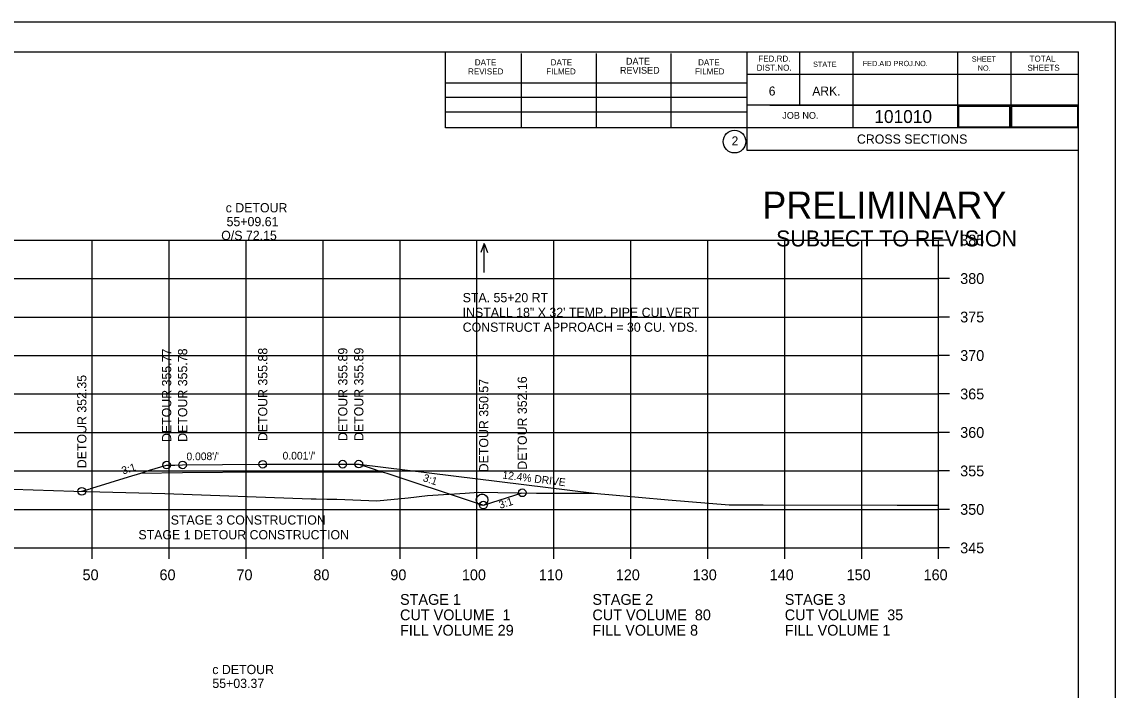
# Model space of a CAD drawing. Extents: x 1630712 to 1632516, y 782146 to 785403.
# Drawn here: x 1632373.8 to 1632515.9, y 784036.5 to 784123.3 of the extents above; entities that cross this region are included whole.
import ezdxf

# ---------------------------------------------------------------- set-up
doc = ezdxf.new("R2010")
doc.units = 0
for name, color, linetype in [('Notes', 7, 'Continuous'), ('Page Number', 7, 'Continuous'), ('R_Axis', 7, 'Continuous'), ('R_Axis Annot', 7, 'Continuous'), ('R_Border', 7, 'Continuous'), ('R_Border Notes', 7, 'Continuous'), ('R_Border Prem', 7, 'Continuous'), ('R_Culvert', 7, 'Continuous'), ('R_Culvert Temporary', 7, 'Continuous'), ('R_Culvert Temporary Annot', 7, 'Continuous'), ('R_Detour Subgrade', 7, 'Continuous'), ('R_Detour Surface', 7, 'Continuous'), ('R_Exist Surface', 7, 'Continuous'), ('R_Grid', 7, 'Continuous'), ('R_No Plot', 7, 'Continuous'), ('R_Water Annot', 7, 'Continuous'), ('R_Xsect Elev Detour', 7, 'Continuous'), ('R_Xsect Slope', 7, 'Continuous'), ('Total_Pages', 7, 'Continuous')]:
    doc.layers.add(name, color=color, linetype=linetype)

msp = doc.modelspace()

# ---------------------------------------------------------------- linework, layer by layer
at = {"layer": 'Page Number'}
msp.add_lwpolyline([(1632495.54, 784109.69), (1632502.21, 784109.69), (1632502.21, 784112.33), (1632495.54, 784112.33)], close=True, dxfattribs=at)
at = {"layer": 'R_Axis'}
for p, q in [((1632492.96, 784054.96), (1632492.96, 784094.96)), ((1632494.36, 784094.96), (1632492.96, 784094.96)), ((1632494.36, 784089.96), (1632492.96, 784089.96)), ((1632494.36, 784084.96), (1632492.96, 784084.96)), ((1632494.36, 784079.96), (1632492.96, 784079.96)), ((1632494.36, 784074.96), (1632492.96, 784074.96)), ((1632494.36, 784069.96), (1632492.96, 784069.96)), ((1632494.36, 784064.96), (1632492.96, 784064.96)), ((1632494.36, 784059.96), (1632492.96, 784059.96)), ((1632212.96, 784054.96), (1632492.96, 784054.96)), ((1632382.96, 784053.56), (1632382.96, 784054.96)), ((1632392.96, 784053.56), (1632392.96, 784054.96)), ((1632402.96, 784053.56), (1632402.96, 784054.96)), ((1632412.96, 784053.56), (1632412.96, 784054.96)), ((1632422.96, 784053.56), (1632422.96, 784054.96)), ((1632432.96, 784053.56), (1632432.96, 784054.96)), ((1632442.96, 784053.56), (1632442.96, 784054.96)), ((1632452.96, 784053.56), (1632452.96, 784054.96)), ((1632462.96, 784053.56), (1632462.96, 784054.96)), ((1632472.96, 784053.56), (1632472.96, 784054.96)), ((1632482.96, 784053.56), (1632482.96, 784054.96)), ((1632492.96, 784053.56), (1632492.96, 784054.96)), ((1632494.36, 784054.96), (1632492.96, 784054.96))]:
    msp.add_line(p, q, dxfattribs=at)
at = {"layer": 'R_Border'}
for p, q in [((1632194.96, 784119.42), (1632511.14, 784119.42)), ((1632428.88, 784109.54), (1632428.88, 784119.42)), ((1632438.74, 784109.54), (1632438.74, 784119.22)), ((1632448.5, 784109.54), (1632448.5, 784119.22)), ((1632458.18, 784109.54), (1632458.18, 784119.22)), ((1632468.04, 784119.42), (1632468.04, 784106.62)), ((1632474.88, 784119.42), (1632474.88, 784112.48)), ((1632481.82, 784119.42), (1632481.82, 784109.54)), ((1632495.4, 784119.42), (1632495.4, 784109.54)), ((1632502.34, 784119.42), (1632502.34, 784109.54)), ((1632511.14, 783913.96), (1632511.14, 784119.42)), ((1632511.14, 784116.48), (1632468.04, 784116.48)), ((1632511.14, 784116.5), (1632511.14, 784116.5)), ((1632428.88, 784115.4), (1632468.04, 784115.4)), ((1632428.88, 784113.54), (1632468.04, 784113.54)), ((1632511.14, 784112.48), (1632468.04, 784112.48)), ((1632471, 784112.48), (1632511.14, 784112.48)), ((1632428.88, 784109.54), (1632428.88, 784111.6)), ((1632428.88, 784111.6), (1632468.04, 784111.6)), ((1632511.14, 784109.54), (1632428.88, 784109.54)), ((1632468.04, 784106.62), (1632511.14, 784106.62))]:
    msp.add_line(p, q, dxfattribs=at)
msp.add_circle((1632466.43, 784107.75), 1.47, dxfattribs=at)
at = {"layer": 'R_Culvert'}
msp.add_circle((1632433.63, 784061.21), 0.75, dxfattribs=at)
at = {"layer": 'R_Culvert Temporary'}
msp.add_circle((1632433.63, 784061.21), 0.755, dxfattribs=at)
at = {"layer": 'R_Detour Subgrade'}
msp.add_lwpolyline([(1632389.29, 784064.69), (1632394.7, 784064.74), (1632405.12, 784064.83), (1632415.52, 784064.84), (1632420.61, 784064.86)], dxfattribs=at)
at = {"layer": 'R_Detour Surface'}
msp.add_line((1632417.6, 784065.85), (1632448.19, 784062.06), dxfattribs=at)
msp.add_lwpolyline([(1632381.6, 784062.31), (1632382.71, 784062.65), (1632382.74, 784062.66), (1632382.91, 784062.71), (1632387.66, 784064.19), (1632389.29, 784064.69), (1632390.42, 784065.04), (1632392.62, 784065.72), (1632393.69, 784065.73), (1632394.7, 784065.74), (1632405.1, 784065.83), (1632405.1, 784065.83), (1632405.12, 784065.83), (1632406.34, 784065.83), (1632406.5, 784065.83), (1632406.54, 784065.83), (1632406.82, 784065.83), (1632415.52, 784065.84), (1632416.77, 784065.85), (1632417.6, 784065.85), (1632419.06, 784065.37), (1632420.61, 784064.86), (1632420.96, 784064.74), (1632421.23, 784064.65), (1632432.32, 784061.01), (1632433.79, 784060.52), (1632434.88, 784060.87), (1632438.84, 784062.12)], dxfattribs=at)
at = {"layer": 'R_Exist Surface'}
msp.add_lwpolyline([(1632372.65, 784062.59), (1632380.58, 784062.33), (1632392.38, 784062.03), (1632411.42, 784061.35), (1632412.06, 784061.34), (1632413.46, 784061.29), (1632414.75, 784061.3), (1632419.95, 784061.07), (1632424.03, 784061.46), (1632426.54, 784061.78), (1632431.41, 784062.08), (1632433.17, 784062.18), (1632440.7, 784062.09), (1632448.19, 784062.06), (1632449.04, 784061.97), (1632450.08, 784061.89), (1632457.81, 784061.19), (1632465.72, 784060.57), (1632469.07, 784060.56), (1632470.16, 784060.56), (1632487.55, 784060.52), (1632492.96, 784060.53)], dxfattribs=at)
at = {"layer": 'R_Grid'}
for p, q in [((1632212.96, 784094.96), (1632492.96, 784094.96)), ((1632382.96, 784054.96), (1632382.96, 784094.96)), ((1632392.96, 784054.96), (1632392.96, 784094.96)), ((1632402.96, 784054.96), (1632402.96, 784094.96)), ((1632412.96, 784054.96), (1632412.96, 784094.96)), ((1632422.96, 784054.96), (1632422.96, 784094.96)), ((1632432.96, 784054.96), (1632432.96, 784094.96)), ((1632442.96, 784054.96), (1632442.96, 784094.96)), ((1632452.96, 784054.96), (1632452.96, 784094.96)), ((1632462.96, 784054.96), (1632462.96, 784094.96)), ((1632472.96, 784054.96), (1632472.96, 784094.96)), ((1632482.96, 784054.96), (1632482.96, 784094.96)), ((1632492.96, 784054.96), (1632492.96, 784094.96)), ((1632212.96, 784089.96), (1632492.96, 784089.96)), ((1632212.96, 784084.96), (1632492.96, 784084.96)), ((1632212.96, 784079.96), (1632492.96, 784079.96)), ((1632212.96, 784074.96), (1632492.96, 784074.96)), ((1632212.96, 784069.96), (1632492.96, 784069.96)), ((1632212.96, 784064.96), (1632492.96, 784064.96)), ((1632212.96, 784059.96), (1632492.96, 784059.96)), ((1632212.96, 784054.96), (1632492.96, 784054.96))]:
    msp.add_line(p, q, dxfattribs=at)
at = {"layer": 'R_No Plot'}
msp.add_line((1632182.56, 784123.31), (1632515.9, 784123.31), dxfattribs=at)
msp.add_lwpolyline([(1632182.56, 784123.31), (1632515.9, 784123.31), (1632515.9, 783909.97), (1632182.56, 783909.97)], close=True, dxfattribs=at)
for centre in [(1632392.62, 784065.72), (1632394.7, 784065.74), (1632405.12, 784065.83), (1632415.52, 784065.84), (1632417.6, 784065.85), (1632381.6, 784062.31), (1632438.84, 784062.12), (1632433.79, 784060.52)]:
    msp.add_circle(centre, 0.5, dxfattribs=at)
at = {"layer": 'R_Water Annot'}
for p, q in [((1632433.9, 784094.52), (1632433.48, 784093.36)), ((1632433.9, 784090.75), (1632433.9, 784094.52)), ((1632433.9, 784094.52), (1632434.32, 784093.36))]:
    msp.add_line(p, q, dxfattribs=at)
at = {"layer": 'Total_Pages'}
msp.add_lwpolyline([(1632502.44, 784109.69), (1632511.05, 784109.69), (1632511.05, 784112.33), (1632502.44, 784112.33)], close=True, dxfattribs=at)

# ---------------------------------------------------------------- texts
at = {"layer": 'Notes'}
for s, p in [('c DETOUR', (1632400.3, 784098.56)), ('55+09.61', (1632400.42, 784096.76)), ('O/S 72.15', (1632399.72, 784094.96)), ('STAGE 3 CONSTRUCTION', (1632393.16, 784057.99)), ('STAGE 1 DETOUR CONSTRUCTION', (1632388.96, 784056.07)), ('c DETOUR', (1632398.56, 784038.56)), ('55+03.37', (1632398.57, 784036.76))]:
    msp.add_text(s, height=1.2, dxfattribs=at).set_placement(p)
msp.add_text('12.4% DRIVE', height=1, rotation=352.933, dxfattribs=at).set_placement((1632436.23, 784063.98))
at = {"layer": 'R_Axis Annot'}
for s, p in [('385', (1632495.76, 784094.26)), ('380', (1632495.76, 784089.26)), ('375', (1632495.76, 784084.26)), ('370', (1632495.76, 784079.26)), ('365', (1632495.76, 784074.26)), ('360', (1632495.76, 784069.26)), ('355', (1632495.76, 784064.26)), ('350', (1632495.76, 784059.26)), ('345', (1632495.76, 784054.26)), ('50', (1632381.7, 784050.76)), ('60', (1632391.7, 784050.76)), ('70', (1632401.7, 784050.76)), ('80', (1632411.7, 784050.76)), ('90', (1632421.7, 784050.76)), ('100', (1632431, 784050.76)), ('110', (1632441, 784050.76)), ('120', (1632451, 784050.76)), ('130', (1632461, 784050.76)), ('140', (1632471, 784050.76)), ('150', (1632481, 784050.76)), ('160', (1632491, 784050.76)), ('STAGE 1', (1632422.96, 784047.56)), ('STAGE 2', (1632447.96, 784047.56)), ('STAGE 3', (1632472.96, 784047.56)), ('CUT VOLUME  1', (1632422.96, 784045.56)), ('CUT VOLUME  80', (1632447.96, 784045.56)), ('CUT VOLUME  35', (1632472.96, 784045.56)), ('FILL VOLUME 29', (1632422.96, 784043.56)), ('FILL VOLUME 8', (1632447.96, 784043.56)), ('FILL VOLUME 1', (1632472.96, 784043.56))]:
    msp.add_text(s, height=1.4, dxfattribs=at).set_placement(p)
at = {"layer": 'R_Border'}
for s, height, p in [('DATE', 0.782, (1632432.68, 784117.66)), ('DATE', 0.782, (1632442.54, 784117.66)), ('DATE', 0.879, (1632452.32, 784117.76)), ('DATE', 0.782, (1632461.7, 784117.66)), ('DIST.NO.', 0.782, (1632469.32, 784116.96)), ('FED.RD.', 0.782, (1632469.52, 784118.14)), ('STATE', 0.684, (1632476.64, 784117.46)), ('FED.AID PROJ.NO.', 0.684, (1632483.1, 784117.56)), ('SHEET', 0.684, (1632497.26, 784118.14)), ('NO.', 0.684, (1632498.04, 784116.96)), ('SHEETS', 0.782, (1632504.5, 784116.96)), ('TOTAL', 0.782, (1632504.78, 784118.14)), ('REVISED', 0.782, (1632431.8, 784116.48)), ('FILMED', 0.782, (1632441.96, 784116.48)), ('REVISED', 0.879, (1632451.54, 784116.58)), ('FILMED', 0.782, (1632461.3, 784116.48)), ('6', 1.17, (1632470.88, 784113.74)), ('ARK.', 1.172, (1632476.54, 784113.74)), ('JOB NO.', 0.879, (1632472.64, 784110.72)), ('2', 1.17, (1632466.05, 784107.26))]:
    msp.add_text(s, height=height, rotation=360, dxfattribs=at).set_placement(p)
at = {"layer": 'R_Border Notes'}
for s, height, p in [('101010', 1.68, (1632484.6, 784110.17)), ('CROSS SECTIONS', 1.2, (1632482.34, 784107.48))]:
    msp.add_text(s, height=height, dxfattribs=at).set_placement(p)
at = {"layer": 'R_Border Prem'}
for s, height, p in [('PRELIMINARY', 3.5, (1632470.03, 784097.76)), ('SUBJECT TO REVISION', 2.0751, (1632471.84, 784094.13))]:
    msp.add_text(s, height=height, rotation=360, dxfattribs=at).set_placement(p)
at = {"layer": 'R_Culvert Temporary Annot'}
for s, p in [('STA. 55+20 RT', (1632431.1, 784086.88)), ('INSTALL 18" X 32\' TEMP. PIPE CULVERT', (1632431.1, 784084.96)), ('CONSTRUCT APPROACH = 30 CU. YDS.', (1632431.1, 784083.04))]:
    msp.add_text(s, height=1.2, dxfattribs=at).set_placement(p)
at = {"layer": 'R_Xsect Elev Detour'}
for s, p in [('DETOUR 355.77', (1632393.22, 784068.72)), ('DETOUR 355.78', (1632395.3, 784068.74)), ('DETOUR 355.88', (1632405.72, 784068.83)), ('DETOUR 355.89', (1632416.12, 784068.84)), ('DETOUR 355.89', (1632418.2, 784068.85)), ('DETOUR 352.35', (1632382.2, 784065.31)), ('DETOUR 350.57', (1632434.44, 784064.78)), ('DETOUR 352.16', (1632439.44, 784065.12))]:
    msp.add_text(s, height=1.2, rotation=90, dxfattribs=at).set_placement(p)
at = {"layer": 'R_Xsect Slope'}
for s, rotation, p in [("0.008'/'", 0.5032, (1632395.21, 784066.34)), ("0.001'/'", 0.0828, (1632407.7, 784066.44)), ('3:1', 17.2166, (1632386.96, 784064.49)), ('3:1', 341.7919, (1632425.85, 784063.66)), ('3:1', 17.5265, (1632435.97, 784060.03))]:
    msp.add_text(s, height=1, rotation=rotation, dxfattribs=at).set_placement(p)

doc.saveas('drawing.dxf')
